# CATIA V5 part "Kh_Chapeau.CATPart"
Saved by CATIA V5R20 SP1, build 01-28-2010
Part number: Chapeau
Bounding box of the stored display mesh (mm): x -41.992 to 41.992, y -6 to 0, z -41.992 to 41.992
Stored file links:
  G:\Khaled_CFAO_2011\SIL\SIL_GR1\tmerino\Khaled\CAD_Thinkmotion\Kh_Chapeau.CATPart
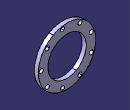
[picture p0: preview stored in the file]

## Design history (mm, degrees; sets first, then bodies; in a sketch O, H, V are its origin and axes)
Body1 (main body)
  Sketch1 on yz-plane, origin (0, 0, 0), H (0, 1, 0), V (0, 0, 1)
    line L1 (-6, -28) -> (0, -28)
    line L2 (0, -28) -> (0, -42)
    line L3 (0, -42) -> (-6, -42)
    line L4 (-6, -42) -> (-6, -28)
    distance H L1 = 28
    distance L4 L2 = 6
    distance L3 H = 42
    distance L2 V = 0
    horizontal: L1 H, L3 H
    vertical: L2 V, L4 V
  Shaft1: profile Sketch1, axis Sketch1.H, angle 360
  Sketch2 on face of Shaft1 from Sketch1.L4, origin (34.7794, -6, 7.6368), H (1, 0, 0), V (0, 0, 1)
    point P1 (3.2206, -7.6368)
    reference intersected line E1 through (0, -7.6368) direction (-1, 0) from xy-plane
    reference intersected line E2 through (-34.7794, 0) direction (0, 1) from yz-plane
    distance E1 P1 = 0
    distance E2 P1 = 38
  Hole1: placed by Sketch2, at (38, -6, 0) direction (0, 1, 0), diameter 6, through (limit type 3)
  CircPattern1: of Hole1, instances 9, angular step 40, axis from face of Shaft1 from Sketch1.L4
